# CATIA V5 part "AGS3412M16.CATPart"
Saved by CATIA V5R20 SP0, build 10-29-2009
Part number: AGS3412M16
Definition: NONE
Nomenclature: AGS3412M16
Source: Unknown
Description: AGS3412M16
Bounding box of the stored display mesh (mm): x -33 to 35, y -32.5 to 32.5, z -32.5 to 32.5
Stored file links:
  C:\Users\Utente\Desktop\IO LAVORO\3D X SITO CF\X SITO\PLASTICA\AGS\AGS3412M16.CATPart
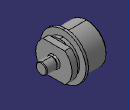
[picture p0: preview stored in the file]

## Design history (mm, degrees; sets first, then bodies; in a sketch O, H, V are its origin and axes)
Body1 "AGS3412M16" (main body)
  Solid1: solid without history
